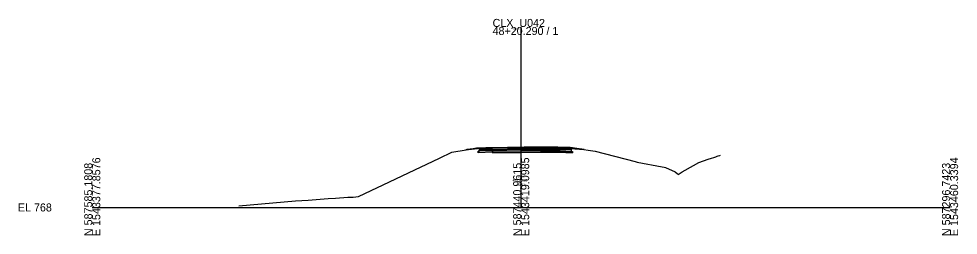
# Model space of a CAD drawing. Extents: x -26 to 1603, y -10 to 5557.
# Drawn here: x 1274.3 to 1602.8, y 490.3 to 565.9 of the extents above; entities that cross this region are included whole.
import ezdxf

# ---------------------------------------------------------------- set-up
doc = ezdxf.new("R2010")
doc.units = 0
for name, color, linetype in [('GK_Cells', 7, 'Continuous'), ('XS_P_Annotation', 7, 'Continuous'), ('XS_P_Earthwork_Shapes', 7, 'Continuous'), ('XS_P_Finished_Grade', 7, 'Continuous'), ('XS_P_Pavt_Layers', 7, 'Continuous'), ('XS_P_Pavt_Surface', 7, 'Continuous'), ('XS_P_Shoulder_Layers', 7, 'Continuous'), ('XS_P_Shoulder_Surface', 7, 'Continuous'), ('XS_P_Subgrade', 7, 'Continuous'), ('XS_X_Ground_Line', 7, 'Continuous'), ('XS_X_Pavt', 7, 'Continuous')]:
    doc.layers.add(name, color=color, linetype=linetype)

msp = doc.modelspace()

# ---------------------------------------------------------------- linework, layer by layer
at = {"layer": 'GK_Cells'}
for p, q in [((1450, 500), (1450, 563.08)), ((1300, 500), (1450, 500)), ((1450, 500), (1600, 500))]:
    msp.add_line(p, q, dxfattribs=at)
at = {"layer": 'XS_P_Earthwork_Shapes'}
for points in [[(1431, 520.28), (1430.61, 520.08), (1432.67, 520.42)], [(1431, 520.28), (1430.61, 520.08), (1432.67, 520.42)], [(1431, 520.28), (1430.61, 520.08), (1432.67, 520.42)], [(1432.67, 520.42), (1434.41, 520.7), (1435.81, 520.76), (1435.81, 520.68)], [(1435.81, 520.68), (1435.81, 520.76), (1434.41, 520.7), (1432.67, 520.42)], [(1435.81, 520.68), (1435.81, 520.76), (1434.41, 520.7), (1432.67, 520.42)], [(1438.07, 520.11), (1439.93, 520.13), (1439.93, 519.32), (1434.97, 519.12), (1434.97, 519.62), (1435.47, 519.64), (1435.47, 520.39), (1435.81, 520.41), (1435.81, 520.01), (1437.6, 520.09)], [(1435.47, 519.64), (1435.47, 520.39), (1435.81, 520.41), (1435.81, 520.01), (1437.6, 520.09), (1438.07, 520.11), (1439.93, 520.13), (1439.93, 519.32), (1434.97, 519.12), (1434.97, 519.62)], [(1435.47, 519.64), (1435.47, 520.39), (1435.81, 520.41), (1435.81, 520.01), (1437.6, 520.09), (1438.07, 520.11), (1439.93, 520.13), (1439.93, 519.32), (1434.97, 519.12), (1434.97, 519.62)], [(1462.83, 520.28), (1463.4, 520.27), (1463.72, 520.26), (1466.67, 520.21), (1467.14, 520.15), (1467.14, 520.37), (1467.14, 520.64), (1467.14, 520.9), (1466.67, 520.96), (1463.72, 521.01), (1462.83, 521.03), (1452.36, 521.02), (1451.1, 521.02), (1450, 521), (1445.26, 520.95), (1438.07, 520.86), (1437.6, 520.84), (1435.81, 520.76), (1435.81, 520.68), (1435.81, 520.41), (1435.81, 520.01), (1437.6, 520.09), (1438.07, 520.11), (1439.93, 520.13), (1445.26, 520.2), (1450, 520.25), (1451.1, 520.27), (1452.36, 520.27)], [(1467.14, 520.64), (1467.14, 520.37), (1467.14, 520.15), (1466.67, 520.21), (1463.72, 520.26), (1463.4, 520.27), (1462.83, 520.28), (1452.36, 520.27), (1451.1, 520.27), (1450, 520.25), (1445.26, 520.2), (1439.93, 520.13), (1438.07, 520.11), (1437.6, 520.09), (1435.81, 520.01), (1435.81, 520.41), (1435.81, 520.68), (1435.81, 520.76), (1437.6, 520.84), (1438.07, 520.86), (1445.26, 520.95), (1450, 521), (1451.1, 521.02), (1452.36, 521.02), (1462.83, 521.03), (1463.72, 521.01), (1466.67, 520.96), (1467.14, 520.9)], [(1467.14, 520.64), (1467.14, 520.37), (1467.14, 520.15), (1466.67, 520.21), (1463.72, 520.26), (1463.4, 520.27), (1462.83, 520.28), (1452.36, 520.27), (1451.1, 520.27), (1450, 520.25), (1445.26, 520.2), (1439.93, 520.13), (1438.07, 520.11), (1437.6, 520.09), (1435.81, 520.01), (1435.81, 520.41), (1435.81, 520.68), (1435.81, 520.76), (1437.6, 520.84), (1438.07, 520.86), (1445.26, 520.95), (1450, 521), (1451.1, 521.02), (1452.36, 521.02), (1462.83, 521.03), (1463.72, 521.01), (1466.67, 520.96), (1467.14, 520.9)], [(1462.83, 520.28), (1463.4, 520.27), (1463.4, 519.27), (1463.36, 519.27), (1462.83, 519.28), (1450, 519.48), (1439.97, 519.32), (1439.93, 519.32), (1439.93, 520.13), (1445.26, 520.2), (1450, 520.25), (1451.1, 520.27), (1452.36, 520.27)], [(1463.36, 519.27), (1462.83, 519.28), (1450, 519.48), (1439.97, 519.32), (1439.93, 519.32), (1439.93, 520.13), (1445.26, 520.2), (1450, 520.25), (1451.1, 520.27), (1452.36, 520.27), (1462.83, 520.28), (1463.4, 520.27), (1463.4, 519.27)], [(1463.36, 519.27), (1462.83, 519.28), (1450, 519.48), (1439.97, 519.32), (1439.93, 519.32), (1439.93, 520.13), (1445.26, 520.2), (1450, 520.25), (1451.1, 520.27), (1452.36, 520.27), (1462.83, 520.28), (1463.4, 520.27), (1463.4, 519.27)], [(1467.48, 519.61), (1467.98, 519.59), (1467.98, 519.08), (1463.4, 519.27), (1463.4, 520.27), (1463.72, 520.26), (1466.67, 520.21), (1467.14, 520.15), (1467.14, 520.37), (1467.48, 520.36)], [(1467.48, 519.61), (1467.98, 519.59), (1467.98, 519.08), (1463.4, 519.27), (1463.4, 520.27), (1463.72, 520.26), (1466.67, 520.21), (1467.14, 520.15), (1467.14, 520.37), (1467.48, 520.36)], [(1467.98, 519.08), (1463.4, 519.27), (1463.4, 520.27), (1463.72, 520.26), (1466.67, 520.21), (1467.14, 520.15), (1467.14, 520.37), (1467.48, 520.36), (1467.48, 519.61), (1467.98, 519.59)], [(1469.41, 520.59), (1472.02, 520.23), (1467.14, 520.64), (1467.14, 520.9)], [(1467.14, 520.64), (1472.02, 520.23), (1469.41, 520.59), (1467.14, 520.9)], [(1467.14, 520.64), (1472.02, 520.23), (1469.41, 520.59), (1467.14, 520.9)]]:
    msp.add_lwpolyline(points, close=True, dxfattribs=at)
at = {"layer": 'XS_P_Finished_Grade'}
for p, q in [((1431, 520.28), (1430.61, 520.08)), ((1435.81, 520.68), (1431, 520.28)), ((1467.14, 520.64), (1472.02, 520.23))]:
    msp.add_line(p, q, dxfattribs=at)
at = {"layer": 'XS_P_Pavt_Layers'}
for p, q in [((1434.97, 519.62), (1434.97, 519.12)), ((1435.47, 520.39), (1435.47, 519.64)), ((1435.81, 520.68), (1435.81, 520.41)), ((1450, 520.88), (1439.93, 520.72)), ((1450, 520.73), (1439.93, 520.57)), ((1450.02, 519.98), (1439.95, 519.82)), ((1450.02, 519.48), (1439.95, 519.32)), ((1449.98, 519.98), (1463.38, 519.77)), ((1449.98, 519.48), (1463.38, 519.27)), ((1450, 520.88), (1463.4, 520.66)), ((1450, 520.73), (1463.4, 520.52)), ((1467.14, 520.64), (1467.14, 520.37)), ((1467.48, 520.36), (1467.48, 519.61)), ((1467.98, 519.59), (1467.98, 519.08))]:
    msp.add_line(p, q, dxfattribs=at)
at = {"layer": 'XS_P_Pavt_Surface'}
for q in [(1439.93, 520.84), (1463.4, 520.79)]:
    msp.add_line((1450, 521), q, dxfattribs=at)
at = {"layer": 'XS_P_Shoulder_Layers'}
for p, q in [((1439.97, 519.82), (1434.97, 519.62)), ((1439.99, 519.32), (1434.97, 519.12)), ((1439.94, 520.57), (1435.47, 520.39)), ((1439.93, 520.72), (1435.81, 520.55)), ((1463.34, 519.27), (1467.98, 519.08)), ((1463.36, 519.77), (1467.98, 519.59)), ((1463.39, 520.52), (1467.48, 520.36)), ((1463.4, 520.66), (1467.14, 520.52))]:
    msp.add_line(p, q, dxfattribs=at)
at = {"layer": 'XS_P_Shoulder_Surface'}
for p, q in [((1439.93, 520.84), (1435.81, 520.68)), ((1463.4, 520.79), (1467.14, 520.64))]:
    msp.add_line(p, q, dxfattribs=at)
at = {"layer": 'XS_P_Subgrade'}
msp.add_lwpolyline([(1467.14, 520.64), (1467.14, 520.37), (1467.48, 520.36), (1467.48, 519.61), (1467.98, 519.59), (1467.98, 519.08), (1463.36, 519.27), (1450, 519.48), (1439.97, 519.32), (1434.97, 519.12), (1434.97, 519.62), (1435.47, 519.64), (1435.47, 520.39), (1435.81, 520.41), (1435.81, 520.68)], dxfattribs=at)
at = {"layer": 'XS_X_Ground_Line'}
msp.add_lwpolyline([(1351.23, 500.53), (1371.05, 502.34), (1375.55, 502.53), (1382.45, 503.1), (1385.02, 503.27), (1389.41, 503.56), (1391.27, 503.65), (1393.09, 503.81), (1421.44, 517.27), (1425.7, 519.3), (1426.44, 519.41), (1434.41, 520.7), (1437.6, 520.84), (1438.07, 520.86), (1445.26, 520.95), (1450, 521), (1451.1, 521.02), (1452.36, 521.02), (1462.83, 521.03), (1463.72, 521.01), (1466.67, 520.96), (1469.41, 520.59), (1475.83, 519.72), (1489.81, 516.03), (1490.58, 515.88), (1499.29, 514.25), (1500.06, 514.1), (1500.44, 513.93), (1503.87, 512.41), (1504.59, 511.82), (1504.91, 511.57), (1505.92, 512.16), (1506.34, 512.4), (1510.27, 514.71), (1512.11, 515.73), (1513.73, 516.28), (1515.4, 516.84), (1516.55, 517.23), (1517.39, 517.51), (1518.03, 517.73), (1518.53, 517.9), (1518.93, 518.04), (1519.42, 518.18), (1519.73, 518.26)], dxfattribs=at)
at = {"layer": 'XS_X_Pavt'}
for p, q in [((1435.81, 520.76), (1435.81, 520.01)), ((1435.81, 520.01), (1437.6, 520.09)), ((1437.6, 520.09), (1438.07, 520.11)), ((1438.07, 520.11), (1439.93, 520.13)), ((1439.93, 520.13), (1445.26, 520.2)), ((1439.93, 520.13), (1439.93, 519.13)), ((1439.93, 519.13), (1445.26, 519.2)), ((1445.26, 520.2), (1450, 520.25)), ((1445.26, 519.2), (1450, 519.25)), ((1450, 520.25), (1451.1, 520.27)), ((1450, 519.25), (1451.1, 519.27)), ((1451.1, 520.27), (1452.36, 520.27)), ((1451.1, 519.27), (1452.36, 519.27)), ((1452.36, 520.27), (1462.83, 520.28)), ((1452.36, 519.27), (1462.83, 519.28)), ((1462.83, 520.28), (1463.4, 520.27)), ((1462.83, 519.28), (1463.4, 519.27)), ((1463.4, 520.27), (1463.72, 520.26)), ((1463.4, 520.27), (1463.4, 519.27)), ((1463.72, 520.26), (1466.67, 520.21)), ((1466.67, 520.21), (1467.14, 520.15)), ((1467.14, 520.9), (1467.14, 520.15))]:
    msp.add_line(p, q, dxfattribs=at)

# ---------------------------------------------------------------- texts
at = {"layer": 'GK_Cells'}
for s, p in [('CLX_U042', (1440, 563.08)), ('48+20.290 / 1', (1440, 560.28)), ('EL 768', (1274, 498.6))]:
    msp.add_text(s, height=2.8, dxfattribs=at).set_placement(p)
for s, p in [('E 1543377.8576', (1302.8, 490)), ('E 1543419.0985', (1452.8, 490)), ('E 1543460.3394', (1602.8, 490)), ('N 587585.1808', (1300, 490)), ('N 587440.9615', (1450, 490)), ('N 587296.7423', (1600, 490))]:
    msp.add_text(s, height=2.8, rotation=90, dxfattribs=at).set_placement(p)
at = {"layer": 'XS_P_Annotation'}
for s, height, p in [('48+20.29', 0.9, (1446.96, 509.05)), ('789.00', 0.7, (1448.25, 510.55)), ('789.00', 0.7, (1448.25, 507.75))]:
    msp.add_text(s, height=height, dxfattribs=at).set_placement(p)

doc.saveas('drawing.dxf')
